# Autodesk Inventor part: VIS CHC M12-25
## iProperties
Created: 2004-11
Part Number: VIS CHC M12-25
Document SubType Name: Modeling
Designer: Bruno
Manufacturer: Standard
Standards Organization: Custom
Author: Bruno
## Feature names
1. Base1
